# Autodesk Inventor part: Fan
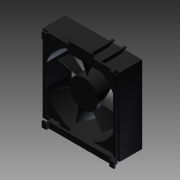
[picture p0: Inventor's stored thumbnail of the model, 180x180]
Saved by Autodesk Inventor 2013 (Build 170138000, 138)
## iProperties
Created: 2006-01
Part Number: Fan
Document SubType Name: Modeling
Designer: Autodesk Inc.
Density: 1 g/cm^3
Categories: <MemberInstance><Categories><Category DisplayName="" Mnemonic="CABLEANDHARNESS" InternalName="e4a7e005-5e42-4d16-b293-125e7f0d0512"><Category DisplayName="" Mne
Mass: 118.529 g
Surface Area: 460.273 cm^2
Volume: 118.529 cm^3
Material: Allgemein
GlobalPropertyList: <PropertyList/>
Company: Autodesk Inc.
Title: PC Demo
Author: Autodesk Inc.
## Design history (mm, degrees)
sketch "Sketch2"
  geometry: L1 (63.52, 0)-(-66.12, 0) reference; L2 (0, -74.04)-(0, 64.84) reference; L3 (-45, 45)-(45, 45); L4 (45, 45)-(45, -45); L5 (45, -45)-(-45, -45); L6 (-45, -45)-(-45, 45)
  constraints: 8 end point, 2 parallel, 1 horizontal, 1 perpendicular, 2 other
  dimensions: "d0" = 90 distance of L3.start L3.end; "d1" = 90 distance of L3.end L4.end
extrude "Extrusion1" new body sketch "Sketch2" stored distance "d2" = 30; taper "d3" = 0 deg
sketch "Sketch4"
  geometry: L1 (0, 0)-(0, -30) reference; L2 (0, -30)-(90, -30) reference; L3 (91.05, -30)-(8.55, -30); L4 (8.55, -30)-(8.55, -34.7); L5 (8.55, -34.7)-(91.05, -34.7); L6 (91.05, -34.7)-(91.05, -30)
  constraints: 8 end point, 2 parallel, 1 horizontal, 1 perpendicular, 1 point on line
  dimensions: "d12" = 4.7 distance of L5.end L3.start; "d13" = 82.5 distance of L4.end L5.end; "d14" = 8.55 distance between parallel lines of L1 L4
extrude "Extrusion3" join sketch "Sketch4" distance "d15" = 95; taper "d16" = 0 deg
sketch "Sketch10"
  geometry: L1 (8.55, -30)-(8.55, -34.7) reference; L2 (8.55, -34.7)-(91.05, -34.7) reference; L3 (16.15, -34.7)-(26.05, -34.7); L4 (26.05, -34.7)-(26.05, -9.2); L5 (26.05, -9.2)-(18.55, -9.2); L6 (18.55, -9.2)-(16.15, -34.7); L7 (26.05, -9.2)-(33.55, -9.2); L8 (33.55, -9.2)-(35.95, -34.7); L9 (26.05, -34.7)-(35.95, -34.7)
  constraints: 14 end point, 3 point on line, 2 collinear, 2 perpendicular, 1 other
  dimensions: "d48" = 9.9 distance of L3.start L3.end; "d49" = 7.5 distance of L4.end L5.end; "d50" = 25.5 distance of L3.end L4.end; "d51" = 17.5 distance between parallel lines of L1 L4
extrude "Extrusion9" join sketch "Sketch10" distance "d52" = 2; taper "d53" = 0 deg
feature "FaceDraft2" dims angle "d54" = 4.5 deg
sketch "Sketch11"
  geometry: L1 (81.45, -34.7)-(-1.05, -34.7) reference; L2 (91.05, -30)-(81.45, -34.7) reference; L3 (73.85, -34.7)-(63.95, -34.7); L4 (63.95, -34.7)-(63.95, -9.2); L5 (63.95, -9.2)-(71.45, -9.2); L6 (71.45, -9.2)-(73.85, -34.7); L7 (63.95, -34.7)-(54.05, -34.7); L8 (63.95, -9.2)-(56.45, -9.2); L9 (56.45, -9.2)-(54.05, -34.7)
  constraints: 14 end point, 3 point on line, 2 perpendicular, 1 parallel, 1 other
  dimensions: "d55" = 9.9 distance of L3.start L3.end; "d56" = 7.5 distance of L4.end L5.end; "d57" = 25.5 distance of L3.end L4.end; "d58" = 17.5 distance between parallel lines of L4 L2
extrude "Extrusion10" join sketch "Sketch11" distance "d59" = 2; taper "d60" = 0 deg
feature "FaceDraft3" dims angle "d61" = 4.5 deg
shell "Shell2" dims "d62" = 2.2
sketch "Sketch12"
  geometry: L1 (33.55, -9.2)-(35.95, -34.7) reference; L2 (35.95, -34.7)-(91.05, -34.7) reference; L3 (8.55, -30)-(8.55, -34.7) reference; L4 (8.55, -34.7)-(16.15, -34.7) reference; L5 (16.15, -34.7)-(18.55, -9.2) reference; L6 (91.05, -34.7)-(8.55, -34.7); L7 (8.55, -34.7)-(8.55, -32.7); L8 (8.55, -32.7)-(91.05, -32.7); L9 (91.05, -32.7)-(91.05, -34.7); L10 (8.55, -34.7)-(10.75, -34.7); L11 (10.75, -34.7)-(10.75, -37.9); L12 (10.75, -37.9)-(8.55, -37.9); L13 (8.55, -37.9)-(8.55, -34.7); L14 (10.75, -37.9)-(5.15, -37.9); L15 (5.15, -37.9)-(5.15, -35.9); L16 (5.15, -35.9)-(10.75, -35.9); L17 (10.75, -35.9)-(10.75, -37.9); L18 (91.05, -32.7)-(88.85, -32.7); L19 (88.85, -32.7)-(88.85, -37.9); L20 (88.85, -37.9)-(91.05, -37.9); L21 (91.05, -37.9)-(91.05, -32.7); L22 (88.85, -37.9)-(94.45, -37.9); L23 (94.45, -37.9)-(94.45, -35.9); L24 (94.45, -35.9)-(88.85, -35.9); L25 (88.85, -35.9)-(88.85, -37.9); L26 (16.338, -32.7)-(16.15, -34.7); L27 (35.762, -32.7)-(35.95, -34.7)
  constraints: 44 end point, 10 parallel, 5 horizontal, 5 perpendicular, 5 point on line, 2 collinear
  dimensions: "d63" = 3.2 distance of L10.end L11.end; "d64" = 2 distance of L6.end L7.end; "d65" = 5.6 distance of L11.end L14.end; "d66" = 2.2 distance of L11.end L12.end; "d67" = 2 distance of L14.end L15.end; "d69" = 2 distance of L22.end L23.end; "d70" = 5.6 distance of L19.end L22.end; "d71" = 2.2 distance of L19.end L20.end; "d72" = 3.2 distance between parallel lines of L2 L22
extrude "Extrusion11" join sketch "Sketch12" distance "d73" = 7.2; taper "d74" = 0 deg
sketch "Sketch13"
  geometry: L1 (0, 0)-(7.788, 0) reference; L2 (27.212, 0)-(82.5, 0) reference; L3 (82.5, 7.2)-(82.5, 0) reference; L4 (27.212, 7.2)-(82.5, 7.2) reference; L5 (27.212, 3.351)-(27.212, 7.2) reference; L6 (27.212, 3.351)-(27.212, 0) reference; L7 (5.563, 0)-(32.475, 0); L8 (32.475, 0)-(32.475, 4.382); L9 (32.475, 4.382)-(5.563, 4.382); L10 (5.563, 4.382)-(5.563, 0)
  constraints: 8 end point, 2 parallel, 1 horizontal, 1 perpendicular, 1 point on line
  dimensions: "d75" = 4.38221 distance of L7.end L8.end
extrude "Extrusion12" join sketch "Sketch13" stored distance "d76" = 7.2; taper "d77" = 0 deg
extrude "Extrusion13" join sketch "Sketch12" distance "d78" = 8; taper "d79" = 0 deg
sketch "Sketch14"
  geometry: L1 (55.11, 9.4)-(-22.99, 9.4) reference; L2 (55.11, 9.4)-(55.11, 2.2) reference; L3 (16.06, 9.4)-(16.06, 12.634); L4 (1.06, 9.4)-(31.06, 9.4); L5 (31.06, 9.4)-(31.06, 11.4); L6 (29.06, 13.4)-(3.06, 13.4); L7 (1.06, 11.4)-(1.06, 9.4); A1 r 2 centre (3.06, 11.4) between (3.06, 13.4) and (1.06, 11.4); A2 r 2 centre (29.06, 11.4) between (31.06, 11.4) and (29.06, 13.4); 2 further points
  constraints: 10 end point, 5 point on line, 4 point on circle, 4 tangent, 3 parallel, 2 centre point, 1 equal radius, 1 horizontal, 1 midpoint, 1 perpendicular, 1 other
  dimensions: "d80" = 30 distance of point (31.06, 13.4) point (1.06, 13.4); "d81" = 4 distance of L4.end point (31.06, 13.4); "d84" = 2 radius of A1
extrude "Extrusion14" join sketch "Sketch14" stored distance "d82" = 8; taper "d83" = 0 deg
workplane "Work Plane1"
sketch "Sketch32"
  geometry: L1 (10.045, 5)-(10.045, 1.197) reference; L2 (10.045, 5)-(0, 5) reference; L3 (0, 0)-(0, 5) reference; L4 (82.5, 0)-(0, 0) reference; L5 (24.955, 1.197)-(24.955, 5) reference; L6 (10.045, 1.197)-(24.955, 1.197) reference; L7 (10.045, 5)-(24.955, 5); L8 (0, 5)-(82.5, 5); L9 (82.5, 5)-(82.5, 0); L10 (82.5, 0)-(0, 0); L11 (0, 0)-(0, 5)
  constraints: 10 end point, 3 parallel, 1 horizontal, 1 perpendicular
extrude "Extrusion31" join sketch "Sketch32" stored distance "d209" = 10; taper "d210" = 0 deg
sketch "Sketch33"
  geometry: L1 (0, 7.2)-(0, 0) reference; L2 (0, 0)-(82.5, 0) reference; L3 (0, 7.2)-(2.2, 7.2); L4 (2.2, 7.2)-(2.2, 0); L5 (2.2, 0)-(0, 0); L6 (0, 0)-(0, 7.2); L7 (82.5, 7.2)-(80.3, 7.2); L8 (80.3, 7.2)-(80.3, 0); L9 (80.3, 0)-(82.5, 0); L10 (82.5, 0)-(82.5, 7.2)
  constraints: 16 end point, 4 parallel, 2 equal length, 2 horizontal, 2 perpendicular, 1 collinear
  dimensions: "d211" = 2.2 distance between parallel lines of L1 L4
extrude "Extrusion32" join sketch "Sketch33" distance "d212" = 1.2; taper "d213" = 0 deg
sketch "Sketch34"
  geometry: L1 (2.2, 0)-(0, 0) reference; L2 (2.2, 7.2)-(-3.4, 7.2); L3 (-3.4, 7.2)-(-3.4, 0); L4 (-3.4, 0)-(2.2, 0); L5 (2.2, 0)-(2.2, 7.2); L6 (80.3, 7.2)-(85.9, 7.2); L7 (85.9, 7.2)-(85.9, 0); L8 (85.9, 0)-(80.3, 0); L9 (80.3, 0)-(80.3, 7.2); L10 (80.3, 0)-(80.3, 7.2) reference
  constraints: 16 end point, 5 collinear, 4 parallel, 2 horizontal, 2 perpendicular
  dimensions: "d214" = 5.6 distance of L2.start L2.end
extrude "Extrusion33" join sketch "Sketch34" stored distance "d216" = 1.2; taper "d217" = 0 deg
sketch "Sketch15"
  geometry: L1 (0, 0)-(0, 30) reference; L2 (0, -2.7)-(-3.6, -2.7); L3 (-3.6, -2.7)-(-3.6, 22.6); L4 (-3.6, 22.6)-(0, 22.6); L5 (0, 22.6)-(0, -2.7); L6 (-7.2, -2.7)-(-7.2, 28.894); L7 (-6.434, 29.055)-(-3.6, 22.6); L8 (-7.2, -2.7)-(-3.6, -2.7); A1 r 0.4 centre (-6.8, 28.894) between (-6.434, 29.055) and (-7.2, 28.894); 1 further point
  constraints: 14 end point, 3 parallel, 2 perpendicular, 2 point on circle, 2 point on line, 2 tangent, 1 centre point, 1 horizontal
  dimensions: "d86" = 25.3 distance of L4.end L2.start; "d87" = 33.5 distance of L6.start point (-7.2, 30.8); "d88" = 3.6 distance of L3.end L4.end; "d89" = 0.4 radius of A1
extrude "Extrusion15" join sketch "Sketch15" distance "d90" = 2.5; taper "d91" = 0 deg
workplane "Work Plane2"
mirror "Mirror1"
sketch "Sketch16"
  geometry: L1 (56.253, -9.2)-(54.06, -32.5) reference; L2 (67.247, -9.2)-(56.253, -9.2) reference; L3 (69.44, -32.5)-(67.247, -9.2) reference; L4 (56.253, -9.2)-(57.119, 0); L5 (57.119, 0)-(66.381, 0); L6 (67.247, -9.2)-(66.381, 0); L7 (56.253, -9.2)-(67.247, -9.2); L8 (69.25, -7)-(54.25, -7) reference; L9 (67.04, -7)-(56.46, -7)
  constraints: 10 end point, 5 point on line, 1 collinear, 1 parallel
  dimensions: "d124" = 7 distance between parallel lines of L9 L5
extrude "Extrusion16" cut sketch "Sketch16" distance "d95" = 2.2; taper "d96" = 0 deg
extrude "Extrusion17" cut sketch "Sketch16" stored distance "d97" = 2.2; taper "d98" = 0 deg
sketch "Sketch22"
  geometry: L1 (56.45, -9.2)-(71.45, -9.2) reference; L2 (69.447, -11.4)-(81.24, -34.7) reference; L3 (65.86, -34.7)-(58.453, -11.4) reference; L4 (58.453, -11.4)-(69.447, -11.4) reference; L5 (69.24, -9.2)-(68.789, -4.4); L6 (68.789, -4.4)-(59.111, -4.4); L7 (59.111, -4.4)-(58.66, -9.2); L8 (65.86, -34.7)-(58.453, -11.4) reference; L9 (69.24, -9.2)-(58.66, -9.2)
  constraints: 8 end point, 2 collinear, 2 point on line, 1 parallel
  dimensions: "d119" = 7 distance between parallel lines of L4 L6
extrude "Extrusion23" cut sketch "Sketch22" stored distance "d120" = 7.2; taper "d121" = 0 deg
sketch "Sketch23"
  geometry: L1 (29.14, -7)-(18.56, -7) reference; L2 (31.54, -32.5)-(29.347, -9.2) reference; L3 (18.353, -9.2)-(16.16, -32.5) reference; L4 (29.347, -9.2)-(18.353, -9.2) reference; L5 (18.353, -9.2)-(18.56, -7); L6 (29.347, -9.2)-(29.14, -7)
  constraints: 4 end point, 2 collinear
extrude "Extrusion24" cut sketch "Sketch23" stored distance "d122" = 7.2; taper "d123" = 0 deg
mirror "Mirror2"
sketch "Sketch24"
  geometry: L1 (-45, -45)-(-45, 45) reference; L2 (45, -45)-(-45, -45) reference; L3 (45, 45)-(45, -45) reference; L4 (-45, 45)-(45, 45) reference; L5 (40.7, 40.7)-(40.7, -40.7); L6 (40.7, -40.7)-(-30.1, -40.7); L7 (-40.7, -30.1)-(-40.7, 40.7); L8 (-40.7, 40.7)-(40.7, 40.7); L9 (-40.7, 40.7)-(-20.7, 40.7); L10 (-20.7, 40.7)-(-20.7, 20.7); L11 (-20.7, 20.7)-(-40.7, 20.7); L12 (-40.7, 20.7)-(-40.7, 40.7); L13 (40.7, 40.7)-(20.7, 40.7); L14 (20.7, 40.7)-(20.7, 20.7); L15 (20.7, 20.7)-(40.7, 20.7); L16 (40.7, 20.7)-(40.7, 40.7); L17 (40.7, -40.7)-(20.7, -40.7); L18 (20.7, -40.7)-(20.7, -20.7); L19 (20.7, -20.7)-(40.7, -20.7); L20 (40.7, -20.7)-(40.7, -40.7); L21 (-40.7, -40.7)-(-32.8, -40.7); L22 (-32.8, -38)-(-32.8, -38); L23 (-38, -32.8)-(-38, -32.8); L24 (-40.7, -32.8)-(-40.7, -40.7); L25 (-51.888, -38)-(-38, -38); L26 (-38, -38)-(-38, -39.653); L27 (-42.297, 38)-(-38, 38); L28 (-38, 38)-(-38, 51.536); L29 (38, 41.948)-(38, 38); L30 (38, 38)-(52.68, 38); L31 (42.448, -38)-(38, -38); L32 (38, -38)-(38, -54.657); C1 r 2.7 at (-38, 38); C2 r 2.7 at (-38, -38); C3 r 2.7 at (38, -38); C4 r 2.7 at (38, 38); A1 r 60 centre (10.531, -10.531) between (-20.7, 40.7) and (-40.7, 20.7); A2 r 60 centre (-10.531, -10.531) between (40.7, 20.7) and (20.7, 40.7); A3 r 60 centre (-10.531, 10.531) between (20.7, -40.7) and (40.7, -20.7); A4 r 2.7 centre (-38, -30.1) between (-40.7, -30.1) and (-38, -32.8); A5 r 2.7 centre (-30.1, -38) between (-32.8, -38) and (-30.1, -40.7); A6 r 5.2 centre (-38, -38) between (-32.8, -38) and (-38, -32.8); 1 further point
  constraints: 56 end point, 12 perpendicular, 12 point on circle, 10 centre point, 8 parallel, 6 point on line, 6 tangent, 4 coincident, 4 horizontal, 1 equal radius, 3 other
  dimensions: "d125" = 4.3 distance between parallel lines of L8 L4; "d126" = 20 distance of L7.end L9.end; "d127" = 20 distance of L9.end L10.end (= d126); "d128" = 20 distance of L13.end L14.end (= d126); "d129" = 20 distance of L14.end L15.end (= d126); "d130" = 20 distance of L18.end L19.end (= d126); "d131" = 20 distance of L17.end L18.end (= d126); "d132" = 60 radius of A1; "d133" = 60 radius of A2; "d134" = 60 radius of A3; "d135" = 7.9 distance of point (-32.8, -32.8) L24.start; "d136" = 7.9 distance of L21.end point (-32.8, -32.8) (= d135); "d137" = 2.7 distance between parallel lines of L6 L25; "d138" = 2.7 distance between parallel lines of L24 L26 (= d137); "d139" = 2.7 distance between parallel lines of L28 L7 (= d140); "d140" = 2.7 distance between parallel lines of L8 L27; "d141" = 2.7 distance between parallel lines of L16 L29; "d142" = 2.7 distance between parallel lines of L8 L30 (= d141); "d143" = 2.7 distance between parallel lines of L6 L31; "d144" = 2.7 distance between parallel lines of L5 L32 (= d143); "d145" = 5.4 diameter of C1; "d146" = 5.4 diameter of C2; "d147" = 5.4 diameter of C3; "d148" = 5.4 diameter of C4; "d149" = 2.7 radius of A4; "d150" = 5.2 radius of A6
extrude "Extrusion25" cut sketch "Sketch24" stored distance "d151" = 7.2; taper "d152" = 0 deg
workplane "Work Plane3"
sketch "Sketch25"
  geometry: L1 (-14.858, 0)-(6.263, 0); L2 (0, 52.522)-(0, 0.625); L3 (0, 0)-(9.659, 2.588); L4 (0, 0)-(-9.659, -2.588); L5 (0, 97.217)-(0, -215.646) reference; L6 (-30.849, 0)-(56.426, 0) reference; A1 r 150 centre (43.958, -142.41) between (9.429, 3.561) and (-9.749, -2.355); A2 r 175 centre (38.988, -170.951) between (9.826, 1.602) and (-9.59, -2.828); A3 r 0.25 centre (-9.659, -2.588) between (-9.749, -2.355) and (-9.59, -2.828); A4 r 1 centre (9.659, 2.588) between (9.826, 1.602) and (9.429, 3.561)
  constraints: 8 end point, 8 point on circle, 4 centre point, 4 tangent, 3 collinear, 2 coincident, 2 point on line, 1 perpendicular
  dimensions: "d154" = 15 deg angle of L1 L3; "d155" = 10 distance of L3.start L4.end; "d156" = 10 distance of L3.start L3.end (= d155); "d157" = 150 radius of A1; "d158" = 175 radius of A2; "d159" = 1 radius of A4; "d160" = 0.25 radius of A3
workplane "Work Plane4"
sketch "Sketch26"
  geometry: L1 (0, 0)-(0, 30) reference; L2 (0, 15)-(45, 15); L3 (45, 15)-(45, 0.38); L4 (45, 15)-(38.505, 18.75); L5 (45, 15)-(51.495, 11.25); L6 (-19.84, 15)-(119.04, 15) reference; L7 (45, -19.012)-(45, 81.17) reference; A1 r 2.5 centre (51.495, 11.25) between (53.995, 11.25) and (53.995, 11.25); A2 r 60 centre (72.66, 66.858) between (37.926, 17.935) and (51.317, 10.783); A3 r 30 centre (60.79, 40.299) between (39.224, 19.445) and (51.648, 11.726); A4 r 1 centre (38.505, 18.75) between (39.224, 19.445) and (37.926, 17.935); A5 r 0.5 centre (51.495, 11.25) between (51.317, 10.783) and (51.648, 11.726)
  constraints: 10 point on circle, 8 end point, 5 centre point, 4 tangent, 3 coincident, 2 collinear, 1 midpoint, 1 perpendicular
  dimensions: "d162" = 30 deg angle of L2 L4; "d163" = 7.5 distance of L2.end L5.end; "d164" = 7.5 distance of L2.end L4.end (= d163); "d168" = 1 radius of A4; "d169" = 0.5 radius of A5; "d170" = 60 radius of A2; "d171" = 30 radius of A3
loft "Loft1" sketch "Sketch26" dims "d172" = 0, "d173" = 90 deg, "d174" = 0, "d175" = 90 deg
pattern_circular "Circular Pattern1" dims angle "d177" = 360 deg
sketch "Sketch27"
  geometry: L1 (31.666, 0)-(-60.811, 0) reference; L2 (0, -68.54)-(0, 31.84) reference; C1 r 17.5 at (0, 0)
  constraints: 2 point on line, 1 centre point
  dimensions: "d179" = 35 diameter of C1
extrude "Extrusion26" join sketch "Sketch27" stored distance "d180" = 22; taper "d181" = 0 deg
sketch "Sketch28"
  geometry: L1 (29.045, 47.9)-(29.045, 49.897) reference; L2 (29.045, 49.897)-(18.455, 49.897) reference; L3 (18.455, 49.897)-(18.455, 47.9) reference; L4 (18.455, 47.9)-(-47.6, 47.9) reference; L5 (-47.6, 47.9)-(-47.6, -47.9) reference; L6 (-47.6, -47.9)-(18.455, -47.9) reference; L7 (18.455, -47.9)-(18.455, -49.897) reference; L8 (18.455, -49.897)-(29.045, -49.897) reference; L9 (29.045, -49.897)-(29.045, -47.9) reference; L10 (29.045, -47.9)-(47.6, -47.9) reference; L11 (47.6, -47.9)-(47.6, 47.9) reference; L12 (47.6, 47.9)-(29.045, 47.9) reference; L13 (16.245, 52.104)-(31.255, 52.104) reference; L14 (31.255, 52.104)-(31.255, 50.1) reference; L15 (31.255, 50.1)-(49.8, 50.1) reference; L16 (49.8, 50.1)-(49.8, -50.1) reference; L17 (49.8, -50.1)-(31.255, -50.1) reference; L18 (31.255, -50.1)-(31.255, -52.104) reference; L19 (31.255, -52.104)-(16.245, -52.104) reference; L20 (16.245, -52.104)-(16.245, -50.1) reference; L21 (16.245, -50.1)-(-15.8, -50.1) reference; L22 (-15.8, -50.1)-(-15.8, -57.3) reference; L23 (-15.8, -57.3)-(-18.3, -57.3) reference; L24 (-18.3, -57.3)-(-18.3, -50.1) reference; L25 (-18.3, -50.1)-(-30.7, -50.1) reference; L26 (-30.7, -50.1)-(-30.7, -57.3) reference; L27 (-30.7, -57.3)-(-33.2, -57.3) reference; L28 (-33.2, -57.3)-(-33.2, -50.1) reference; L29 (-33.2, -50.1)-(-49.8, -50.1) reference; L30 (-49.8, -50.1)-(-49.8, 50.1) reference; L31 (-49.8, 50.1)-(-33.2, 50.1) reference; L32 (-33.2, 50.1)-(-33.2, 57.3) reference; L33 (-33.2, 57.3)-(-30.7, 57.3) reference; L34 (-30.7, 57.3)-(-30.7, 50.1) reference; L35 (-30.7, 50.1)-(-18.3, 50.1) reference; L36 (-18.3, 50.1)-(-18.3, 57.3) reference; L37 (-18.3, 57.3)-(-15.8, 57.3) reference; L38 (-15.8, 57.3)-(-15.8, 50.1) reference; L39 (-15.8, 50.1)-(16.245, 50.1) reference; L40 (16.245, 50.1)-(16.245, 52.104) reference; L41 (36.031, -17.37)-(35.415, -18.651) reference; L42 (8.884, -39.001)-(7.499, -39.317) reference; L43 (-24.953, -31.263)-(-26.064, -30.377) reference; L44 (-40, 0.017)-(-40, 1.438) reference; L45 (-24.926, 31.284)-(-23.815, 32.17) reference; L46 (8.917, 38.993)-(10.303, 38.677) reference; L47 (36.046, 17.34)-(36.663, 16.06) reference; L48 (18.455, 47.9)-(29.045, 47.9); C1 r 45 at (0, 0); A1 r 17.5 centre (0, 0) between (15.735, -7.66) and (16.324, 6.306) reference; A2 r 17.5 centre (0, 0) between (3.822, -17.078) and (15.109, -8.831) reference; A3 r 17.5 centre (0, 0) between (-10.969, -13.636) and (2.516, -17.318) reference; A4 r 17.5 centre (0, 0) between (-17.5, 0.074) and (-11.971, -12.765) reference; A5 r 17.5 centre (0, 0) between (-10.853, 13.728) and (-17.444, 1.401) reference; A6 r 17.5 centre (0, 0) between (3.966, 17.045) and (-9.781, 14.512) reference; A7 r 17.5 centre (0, 0) between (15.799, 7.526) and (5.247, 16.695) reference
  constraints: 96 end point, 21 vertical, 20 horizontal, 14 point on circle, 8 centre point, 1 coincident, 1 perpendicular, 130 other
  dimensions: "d182" = 90 diameter of C1
extrude "Extrusion27" join sketch "Sketch28" stored distance "d183" = 28; taper "d184" = 0 deg
sketch "Sketch29"
  geometry: L1 (-26.104, -42.8)-(-42.8, -42.8) reference; L2 (-29.045, -47.9)-(-47.6, -47.9) reference; L3 (-18.455, -48.558)-(-18.455, -49.897) reference; L4 (47.6, -47.9)-(28.4, -47.9) reference; L5 (-47.6, 47.9)-(-28.314, 47.9) reference; L6 (-42.8, 42.8)-(-26.104, 42.8) reference; L7 (-42.8, 13.898)-(-42.8, 42.8) reference; L8 (42.8, -13.898)-(42.8, -42.8) reference; L9 (-42.8, -42.8)-(-42.8, -13.898) reference; L10 (-26.104, -46.351)-(-26.104, -42.8) reference; L11 (-11.796, -46.351)-(-26.104, -46.351) reference; L12 (-11.796, -43.426)-(-11.796, -46.351) reference; L13 (11, -45)-(11, -47.9) reference; L14 (-9.586, -45)-(11, -45) reference; L15 (-9.586, -47.9)-(-9.586, -45) reference; L16 (11, -47.9)-(-9.586, -47.9) reference; L17 (25.9, -45)-(25.9, -47.9) reference; L18 (13.5, -45)-(25.9, -45) reference; L19 (13.5, -47.9)-(13.5, -45) reference; L20 (25.9, -47.9)-(13.5, -47.9) reference; L21 (28.4, 45)-(28.4, 47.9) reference; L22 (45, 45)-(28.4, 45) reference; L23 (45, -45)-(45, 45) reference; L24 (28.4, -45)-(45, -45) reference; L25 (28.4, -47.9)-(28.4, -45) reference; L26 (47.6, 47.9)-(47.6, -47.9) reference; L27 (28.4, 47.9)-(47.6, 47.9) reference; L28 (25.9, 47.9)-(25.9, 45) reference; L29 (13.5, 47.9)-(25.9, 47.9) reference; L30 (13.5, 45)-(13.5, 47.9) reference; L31 (25.9, 45)-(13.5, 45) reference; L32 (11, 47.9)-(11, 45) reference; L33 (-9.586, 47.9)-(11, 47.9) reference; L34 (-9.586, 45)-(-9.586, 47.9) reference; L35 (11, 45)-(-9.586, 45) reference; L36 (-11.796, 46.351)-(-11.796, 43.426) reference; L37 (-26.104, 42.8)-(-26.104, 46.351) reference; L38 (13.898, 42.8)-(42.8, 42.8) reference; L39 (42.8, 42.8)-(42.8, 13.898) reference; L40 (-28.314, 47.9)-(-28.314, 45) reference; L41 (-47.6, -47.9)-(-47.6, 47.9) reference; L42 (-28.314, -45)-(-28.314, -48.558) reference; L43 (-45, -45)-(-28.314, -45) reference; L44 (-45, 45)-(-45, -45) reference; L45 (-28.314, 45)-(-45, 45) reference; L46 (-29.045, -49.897)-(-29.045, -47.9) reference; L47 (-18.455, -49.897)-(-29.045, -49.897) reference; L48 (-28.314, -48.558)-(-18.455, -48.558) reference; L49 (-26.104, 46.351)-(-11.796, 46.351) reference; L50 (42.8, -42.8)-(13.898, -42.8) reference; C1 r 17.5 at (0, 0) reference; C2 r 39 at (0, 0); C3 r 40.5 at (0, 0); A1 r 45 centre (0, 0) between (13.898, -42.8) and (42.8, -13.898) reference; A2 r 45 centre (0, 0) between (42.8, 13.898) and (13.898, 42.8) reference; A3 r 45 centre (0, 0) between (-42.8, -13.898) and (-11.796, -43.426) reference; A4 r 45 centre (0, 0) between (-11.796, 43.426) and (-42.8, 13.898) reference
  constraints: 2 centre point, 2 coincident
  dimensions: "d185" = 78 diameter of C2; "d218" = 1.5 radial gap between concentric circles of C3 C2
extrude "Extrusion34" cut sketch "Sketch29" stored distance "d219" = 1.2; taper "d220" = 0 deg
sketch "Sketch30"
  geometry: C1 r 17.5 at (0, 0) reference
extrude "Extrusion29" cut sketch "Sketch30" distance "d188" = 2; taper "d189" = 0 deg
workplane "Work Plane5"
sketch "Sketch31"
  geometry: L1 (-38.288, 23.643)-(-17.064, 3.881); L2 (-17.064, 3.881)-(-38.288, 23.643); L3 (-17.453, 1.28)-(-39.409, 21.724); L4 (17.453, -1.28)-(39.409, -21.724); L5 (17.064, -3.881)-(38.288, -23.643); L6 (-1.28, -17.453)-(-21.724, -39.409); L7 (-3.881, -17.064)-(-23.643, -38.288); L8 (3.881, 17.064)-(23.643, 38.288); L9 (3.881, 17.064)-(23.643, 38.288); L10 (21.724, 39.409)-(1.28, 17.453); L11 (0, -73.554)-(0, 61.926) reference; L12 (60.606, 0)-(-65.634, 0) reference; A1 r 45 centre (0, 0) between (-19.197, 40.7) and (-40.7, 19.197) reference; A2 r 45 centre (0, 0) between (40.7, 19.197) and (19.197, 40.7) reference; A3 r 45 centre (0, 0) between (19.197, -40.7) and (40.7, -19.197) reference; A4 r 45 centre (0, 0) between (-40.7, -19.197) and (-19.197, -40.7) reference; 2 further points
  constraints: 20 end point, 10 point on circle, 6 parallel, 2 collinear, 1 coincident, 1 perpendicular, 19 other
  dimensions: "d194" = 30 distance of L3.start L3.end; "d195" = 29 distance of L1.end L2.end; "d196" = 29 distance of L8.start L8.end; "d197" = 30 distance of L10.start L10.end; "d198" = 29 distance of L5.start L5.end; "d199" = 30 distance of L4.start L4.end; "d200" = 30 distance of L6.start L6.end; "d201" = 29 distance of L7.start L7.end; "d202" = 137.043 deg angle of L12 L3; "d205" = 2.16864 distance between parallel lines of L8 L10 (derived)
extrude "Extrusion30" join sketch "Sketch31" distance "d203" = 2.5; taper "d204" = 0 deg
fillet "Fillet2" dims "d206" = 2
fillet "Fillet3" dims "d207" = 1
fillet "Fillet4" dims "d208" = 1
workpoint "Work Point3"
workplane "Work Plane6"
workpoint "Work Point4"
node "+"
node "-"
body "Solid1"
sketch "Sketch35"
  geometry: L1 (34.1, -6.4)-(34.1, -28) reference; L2 (36.6, -6.4)-(34.1, -6.4) reference; L3 (36.6, -28)-(36.6, -6.4) reference; L4 (36.6, -28)-(57.245, -28) reference; L5 (66.055, -19.636)-(58.971, -19.636) reference; L6 (66.055, -19.636)-(66.055, 0) reference; L7 (66.055, 0)-(0, 0) reference; L8 (0, -28)-(0, 0) reference; L9 (0, -28)-(19.2, -28) reference; L10 (19.2, -6.4)-(19.2, -28) reference; L11 (21.7, -6.4)-(19.2, -6.4) reference; L12 (21.7, -28)-(21.7, -6.4) reference; L13 (21.7, -28)-(34.1, -28) reference; L14 (27.9, -16.7)-(27.9, -17.7); 5 further points; 1 other entity
  constraints: 4 midpoint, 2 end point, 2 vertical alignment, 1 horizontal alignment, 1 perpendicular, 1 other
  dimensions: "d221" = 1 distance of L14.start L14.end
sketch "Sketch36"
  geometry: L1 (2.5, 31.594)-(2.5, 0) reference; L2 (0, 31.594)-(2.5, 31.594) reference; L3 (0, 31.594)-(0, 0) reference; L4 (0, 0)-(2.5, 0) reference; L5 (8.7, 15)-(8.7, 14) reference; 1 further point
sketch "Sketch37"
  geometry: 1 further point
node "Projected Loop1"
node "Projected Loop5"
other parameters: "d85" = -16.6, "d92" = -8.7, "d161" = -49.8, "d190" = 14, "d222" = 2
